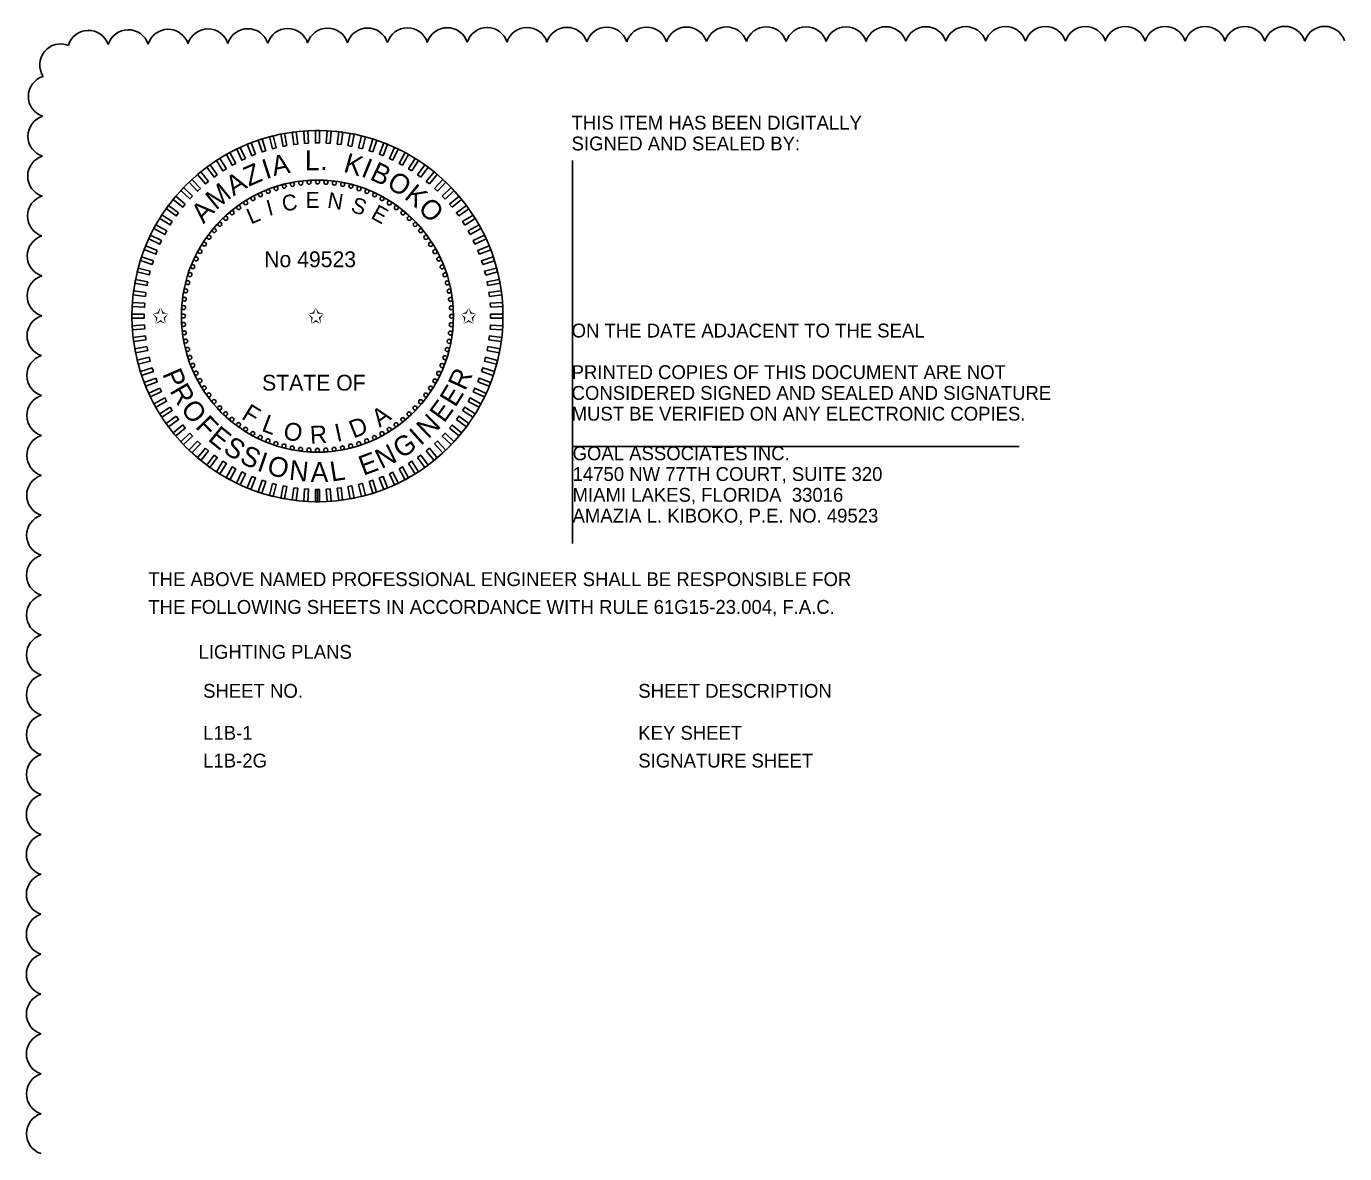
# Model space of a CAD drawing. Extents: x -811.2 to -755.6, y -2295.2 to -2235.1.
# Drawn here: x -783.68 to -777.02, y -2265.59 to -2259.9 of the extents above; entities that cross this region are included whole.
import ezdxf

# ---------------------------------------------------------------- set-up
doc = ezdxf.new("R2010")
doc.units = 0
for name, color, linetype in [('Cloud_dp', 7, 'Continuous'), ('Logo_dp', 7, 'Continuous'), ('NonPlottingEle_dp', 7, 'Continuous'), ('ScratchEle_dp', 7, 'Continuous'), ('TextMisc', 7, 'Continuous'), ('TextNotes', 7, 'Continuous')]:
    doc.layers.add(name, color=color, linetype=linetype)

msp = doc.modelspace()

# ---------------------------------------------------------------- linework, layer by layer
at = {"layer": 'Cloud_dp'}
for centre, start, end in [((-782.5594, -2260.0139), 17.87787, 162.87787), ((-782.3579, -2260.0127), 17.82689, 162.82689), ((-782.1564, -2260.0116), 17.78716, 162.78716), ((-781.9548, -2260.0107), 17.75505, 162.75505), ((-781.7533, -2260.0098), 17.72841, 162.72841), ((-781.5518, -2260.009), 17.70584, 162.70584), ((-781.3502, -2260.0084), 17.6864, 162.6864), ((-781.1487, -2260.0077), 17.66942, 162.66942), ((-780.9472, -2260.0072), 17.65443, 162.65443), ((-780.7456, -2260.0066), 17.64106, 162.64106), ((-780.5441, -2260.0062), 17.62905, 162.62905), ((-780.3425, -2260.0057), 17.61817, 162.61817), ((-780.141, -2260.0053), 17.60826, 162.60826), ((-779.9394, -2260.005), 17.59919, 162.59919), ((-779.7379, -2260.0046), 17.59084, 162.59084), ((-779.5364, -2260.0043), 17.58312, 162.58312), ((-779.3348, -2260.004), 17.57595, 162.57595), ((-779.1333, -2260.0038), 17.56928, 162.56928), ((-778.9317, -2260.0036), 17.56305, 162.56305), ((-778.7302, -2260.0033), 17.55721, 162.55721), ((-778.5286, -2260.0032), 17.55172, 162.55172), ((-778.3271, -2260.003), 17.54655, 162.54655), ((-778.1255, -2260.0028), 17.54167, 162.54167), ((-777.924, -2260.0027), 17.53705, 162.53705), ((-777.7224, -2260.0026), 17.53267, 162.53267), ((-777.5209, -2260.0025), 17.52851, 162.52851), ((-777.3194, -2260.0024), 17.52455, 162.52455), ((-777.1178, -2260.0023), 17.52079, 162.52079), ((-783.3652, -2260.0225), 18.59454, 163.59454), ((-783.1638, -2260.0193), 18.21421, 163.21421), ((-782.9624, -2260.0171), 18.04696, 163.04696), ((-782.7609, -2260.0154), 17.94666, 162.94666), ((-783.5053, -2260.0909), 68.43954, 213.43954), ((-783.563, -2260.2503), 106.80445, 251.80445), ((-783.565, -2260.4517), 107.04367, 252.04367), ((-783.5664, -2260.6532), 107.15618, 252.15618), ((-783.5675, -2260.8547), 107.22533, 252.22533), ((-783.5684, -2261.0562), 107.27338, 252.27338), ((-783.5691, -2261.2578), 107.30928, 252.30928), ((-783.5697, -2261.4593), 107.33743, 252.33743), ((-783.5703, -2261.6608), 107.36027, 252.36027), ((-783.5707, -2261.8624), 107.37928, 252.37928), ((-783.5711, -2262.0639), 107.39543, 252.39543), ((-783.5715, -2262.2655), 107.40937, 252.40937), ((-783.5717, -2262.467), 107.42156, 252.42156), ((-783.572, -2262.6685), 107.43234, 252.43234), ((-783.5722, -2262.8701), 107.44197, 252.44197), ((-783.5724, -2263.0716), 107.45063, 252.45063), ((-783.5726, -2263.2732), 107.45847, 252.45847), ((-783.5727, -2263.4747), 107.46563, 252.46563), ((-783.5728, -2263.6763), 107.47218, 252.47218), ((-783.5729, -2263.8778), 107.47822, 252.47822), ((-783.573, -2264.0794), 107.4838, 252.4838), ((-783.573, -2264.2809), 107.48899, 252.48899), ((-783.5731, -2264.4824), 107.49382, 252.49382), ((-783.5731, -2264.684), 107.49843, 252.49843), ((-783.573, -2264.8855), 107.51148, 252.51148), ((-783.573, -2265.0871), 107.53101, 252.53101), ((-783.5728, -2265.2886), 107.55191, 252.55191), ((-783.5726, -2265.4901), 107.57435, 252.57435)]:
    msp.add_arc(centre, 0.1057, start, end, dxfattribs=at)
at = {"layer": 'Logo_dp'}
for p, q in [((-782.2178, -2262.2978), (-782.218, -2262.2353)), ((-782.2078, -2262.2978), (-782.208, -2262.2353)), ((-782.1978, -2262.2978), (-782.198, -2262.2353))]:
    msp.add_line(p, q, dxfattribs=at)
for points in [[(-782.3618, -2260.4989), (-782.3816, -2260.5026), (-782.3933, -2260.4413), (-782.3735, -2260.4375)], [(-782.3074, -2260.4909), (-782.3274, -2260.4934), (-782.3352, -2260.4315), (-782.3152, -2260.4289)], [(-782.2526, -2260.4864), (-782.2727, -2260.4876), (-782.2767, -2260.4253), (-782.2565, -2260.424)], [(-782.1976, -2260.4853), (-782.2178, -2260.4853), (-782.2178, -2260.4228), (-782.1976, -2260.4228)], [(-782.1427, -2260.4876), (-782.1629, -2260.4864), (-782.1589, -2260.4241), (-782.1388, -2260.4253)], [(-782.088, -2260.4934), (-782.1081, -2260.4909), (-782.1002, -2260.429), (-782.0802, -2260.4315)], [(-782.0338, -2260.5027), (-782.0537, -2260.4989), (-782.042, -2260.4376), (-782.0221, -2260.4413)], [(-782.5712, -2260.5642), (-782.5894, -2260.5728), (-782.616, -2260.5163), (-782.5978, -2260.5077)], [(-782.5205, -2260.543), (-782.5392, -2260.5504), (-782.5622, -2260.4923), (-782.5434, -2260.4849)], [(-782.4685, -2260.525), (-782.4877, -2260.5312), (-782.507, -2260.4718), (-782.4878, -2260.4656)], [(-782.4156, -2260.5102), (-782.4351, -2260.5152), (-782.4506, -2260.4548), (-782.4311, -2260.4498)], [(-781.9803, -2260.5153), (-781.9999, -2260.5103), (-781.9844, -2260.4498), (-781.9648, -2260.4548)], [(-781.9277, -2260.5312), (-781.9469, -2260.525), (-781.9276, -2260.4656), (-781.9084, -2260.4719)], [(-781.8762, -2260.5505), (-781.895, -2260.543), (-781.872, -2260.485), (-781.8532, -2260.4924)], [(-781.826, -2260.5729), (-781.8443, -2260.5643), (-781.8177, -2260.5078), (-781.7994, -2260.5164)], [(-782.6681, -2260.616), (-782.6851, -2260.6268), (-782.7186, -2260.5741), (-782.7015, -2260.5633)], [(-782.6204, -2260.5886), (-782.6381, -2260.5983), (-782.6682, -2260.5436), (-782.6505, -2260.5339)], [(-781.7773, -2260.5984), (-781.795, -2260.5887), (-781.7649, -2260.534), (-781.7473, -2260.5437)], [(-781.7303, -2260.6269), (-781.7474, -2260.6161), (-781.7139, -2260.5634), (-781.6969, -2260.5742)], [(-782.7577, -2260.6796), (-782.7733, -2260.6925), (-782.8131, -2260.6443), (-782.7975, -2260.6315)], [(-782.7139, -2260.6464), (-782.7302, -2260.6583), (-782.7669, -2260.6078), (-782.7506, -2260.5959)], [(-781.6852, -2260.6584), (-781.7016, -2260.6465), (-781.6649, -2260.596), (-781.6485, -2260.6079)], [(-781.6422, -2260.6926), (-781.6578, -2260.6797), (-781.618, -2260.6316), (-781.6024, -2260.6445)], [(-782.7994, -2260.7155), (-782.8141, -2260.7293), (-782.8568, -2260.6838), (-782.8421, -2260.6699)], [(-781.6014, -2260.7294), (-781.6161, -2260.7156), (-781.5734, -2260.6701), (-781.5586, -2260.6839)], [(-782.8755, -2260.7947), (-782.8884, -2260.8102), (-782.9365, -2260.7704), (-782.9237, -2260.7549)], [(-782.8387, -2260.7539), (-782.8525, -2260.7686), (-782.898, -2260.7258), (-782.8842, -2260.7111)], [(-781.563, -2260.7687), (-781.5768, -2260.754), (-781.5313, -2260.7113), (-781.5175, -2260.726)], [(-781.5271, -2260.8104), (-781.54, -2260.7948), (-781.4919, -2260.755), (-781.479, -2260.7706)], [(-782.9097, -2260.8377), (-782.9216, -2260.8541), (-782.9721, -2260.8174), (-782.9603, -2260.801)], [(-781.4939, -2260.8542), (-781.5058, -2260.8379), (-781.4553, -2260.8012), (-781.4434, -2260.8175)], [(-782.9697, -2260.9298), (-782.9794, -2260.9475), (-783.0341, -2260.9174), (-783.0244, -2260.8997)], [(-782.9412, -2260.8828), (-782.952, -2260.8999), (-783.0047, -2260.8664), (-782.9939, -2260.8494)], [(-781.4635, -2260.9), (-781.4744, -2260.883), (-781.4216, -2260.8495), (-781.4108, -2260.8666)], [(-781.4361, -2260.9477), (-781.4458, -2260.93), (-781.3911, -2260.8999), (-781.3814, -2260.9176)], [(-782.9952, -2260.9785), (-783.0038, -2260.9968), (-783.0603, -2260.9702), (-783.0517, -2260.9519)], [(-781.4117, -2260.9969), (-781.4203, -2260.9787), (-781.3638, -2260.9521), (-781.3552, -2260.9704)], [(-783.0176, -2261.0287), (-783.0251, -2261.0475), (-783.0831, -2261.0245), (-783.0757, -2261.0057)], [(-781.3905, -2261.0477), (-781.3979, -2261.0289), (-781.3399, -2261.0059), (-781.3324, -2261.0247)], [(-783.0369, -2261.0802), (-783.0431, -2261.0994), (-783.1025, -2261.0801), (-783.0963, -2261.0609)], [(-781.3725, -2261.0996), (-781.3787, -2261.0804), (-781.3193, -2261.0611), (-781.3131, -2261.0803)], [(-783.0654, -2261.1863), (-783.0692, -2261.2062), (-783.1306, -2261.1945), (-783.1268, -2261.1746)], [(-783.0528, -2261.1328), (-783.0578, -2261.1524), (-783.1183, -2261.1368), (-783.1133, -2261.1173)], [(-781.3577, -2261.1526), (-781.3628, -2261.133), (-781.3023, -2261.1175), (-781.2973, -2261.137)], [(-781.3464, -2261.2063), (-781.3502, -2261.1865), (-781.2888, -2261.1748), (-781.285, -2261.1946)], [(-783.0747, -2261.2405), (-783.0772, -2261.2606), (-783.1391, -2261.2527), (-783.1366, -2261.2327)], [(-781.3384, -2261.2607), (-781.3409, -2261.2407), (-781.279, -2261.2329), (-781.2765, -2261.2529)], [(-783.0805, -2261.2952), (-783.0817, -2261.3153), (-783.1441, -2261.3114), (-783.1428, -2261.2913)], [(-781.3339, -2261.3155), (-781.3351, -2261.2954), (-781.2728, -2261.2915), (-781.2716, -2261.3116)], [(-783.0828, -2261.3501), (-783.0828, -2261.3703), (-783.1453, -2261.3703), (-783.1453, -2261.3501)], [(-781.3328, -2261.3705), (-781.3328, -2261.3503), (-781.2703, -2261.3503), (-781.2703, -2261.3705)], [(-783.0818, -2261.4051), (-783.0805, -2261.4252), (-783.1428, -2261.4291), (-783.1441, -2261.409)], [(-781.3351, -2261.4254), (-781.3339, -2261.4053), (-781.2716, -2261.4092), (-781.2728, -2261.4293)], [(-783.0772, -2261.4599), (-783.0747, -2261.4799), (-783.1366, -2261.4877), (-783.1392, -2261.4677)], [(-781.341, -2261.4801), (-781.3384, -2261.4601), (-781.2765, -2261.4679), (-781.279, -2261.4879)], [(-783.0693, -2261.5143), (-783.0655, -2261.5341), (-783.1268, -2261.5458), (-783.1306, -2261.526)], [(-783.0579, -2261.568), (-783.0529, -2261.5876), (-783.1133, -2261.6031), (-783.1184, -2261.5836)], [(-781.3628, -2261.5878), (-781.3578, -2261.5682), (-781.2973, -2261.5838), (-781.3023, -2261.6033)], [(-781.3502, -2261.5343), (-781.3464, -2261.5144), (-781.2851, -2261.5261), (-781.2889, -2261.546)], [(-783.0432, -2261.621), (-783.0369, -2261.6402), (-783.0963, -2261.6595), (-783.1025, -2261.6403)], [(-781.3788, -2261.6404), (-781.3725, -2261.6212), (-781.3131, -2261.6405), (-781.3194, -2261.6597)], [(-783.0251, -2261.673), (-783.0177, -2261.6917), (-783.0758, -2261.7147), (-783.0832, -2261.6959)], [(-781.398, -2261.6919), (-781.3906, -2261.6731), (-781.3325, -2261.6961), (-781.3399, -2261.7149)], [(-783.0039, -2261.7237), (-782.9953, -2261.7419), (-783.0518, -2261.7685), (-783.0604, -2261.7502)], [(-782.9795, -2261.7729), (-782.9698, -2261.7906), (-783.0245, -2261.8207), (-783.0342, -2261.803)], [(-781.4459, -2261.7908), (-781.4362, -2261.7731), (-781.3815, -2261.8032), (-781.3912, -2261.8209)], [(-781.4204, -2261.7421), (-781.4118, -2261.7238), (-781.3553, -2261.7504), (-781.3639, -2261.7687)], [(-782.9521, -2261.8206), (-782.9413, -2261.8376), (-782.994, -2261.8711), (-783.0048, -2261.854)], [(-781.4745, -2261.8378), (-781.4636, -2261.8207), (-781.4109, -2261.8542), (-781.4217, -2261.8712)], [(-782.9217, -2261.8664), (-782.9099, -2261.8827), (-782.9604, -2261.9194), (-782.9722, -2261.9031)], [(-781.5059, -2261.8829), (-781.494, -2261.8665), (-781.4435, -2261.9032), (-781.4554, -2261.9196)], [(-782.8885, -2261.9102), (-782.8757, -2261.9258), (-782.9238, -2261.9656), (-782.9366, -2261.95)], [(-782.8527, -2261.9519), (-782.8388, -2261.9666), (-782.8844, -2262.0093), (-782.8982, -2261.9946)], [(-781.5769, -2261.9667), (-781.5631, -2261.952), (-781.5176, -2261.9948), (-781.5314, -2262.0095)], [(-781.5401, -2261.9259), (-781.5272, -2261.9104), (-781.4791, -2261.9502), (-781.492, -2261.9657)], [(-782.8142, -2261.9912), (-782.7995, -2262.005), (-782.8423, -2262.0505), (-782.857, -2262.0367)], [(-782.7734, -2262.028), (-782.7579, -2262.0409), (-782.7977, -2262.089), (-782.8132, -2262.0761)], [(-781.6579, -2262.041), (-781.6423, -2262.0281), (-781.6025, -2262.0763), (-781.6181, -2262.0891)], [(-781.6162, -2262.0051), (-781.6015, -2261.9913), (-781.5588, -2262.0368), (-781.5735, -2262.0507)], [(-782.7304, -2262.0622), (-782.7141, -2262.0741), (-782.7508, -2262.1246), (-782.7671, -2262.1127)], [(-782.6853, -2262.0937), (-782.6682, -2262.1045), (-782.7017, -2262.1572), (-782.7187, -2262.1464)], [(-781.7475, -2262.1046), (-781.7305, -2262.0938), (-781.697, -2262.1465), (-781.7141, -2262.1573)], [(-781.7017, -2262.0742), (-781.6854, -2262.0623), (-781.6487, -2262.1129), (-781.665, -2262.1247)], [(-782.6383, -2262.1222), (-782.6206, -2262.1319), (-782.6507, -2262.1866), (-782.6684, -2262.1769)], [(-782.5896, -2262.1477), (-782.5713, -2262.1563), (-782.5979, -2262.2128), (-782.6162, -2262.2042)], [(-782.5394, -2262.1701), (-782.5206, -2262.1776), (-782.5436, -2262.2356), (-782.5624, -2262.2282)], [(-781.8952, -2262.1776), (-781.8764, -2262.1702), (-781.8534, -2262.2283), (-781.8722, -2262.2357)], [(-781.8445, -2262.1564), (-781.8262, -2262.1478), (-781.7996, -2262.2043), (-781.8179, -2262.2129)], [(-781.7952, -2262.132), (-781.7775, -2262.1223), (-781.7474, -2262.177), (-781.7651, -2262.1867)], [(-782.4879, -2262.1894), (-782.4687, -2262.1956), (-782.488, -2262.255), (-782.5072, -2262.2487)], [(-782.4353, -2262.2053), (-782.4157, -2262.2103), (-782.4313, -2262.2708), (-782.4508, -2262.2658)], [(-782.3818, -2262.2179), (-782.362, -2262.2217), (-782.3737, -2262.283), (-782.3935, -2262.2793)], [(-782.3276, -2262.2272), (-782.3076, -2262.2297), (-782.3154, -2262.2916), (-782.3354, -2262.2891)], [(-782.2729, -2262.233), (-782.2528, -2262.2342), (-782.2567, -2262.2966), (-782.2768, -2262.2953)], [(-782.218, -2262.2353), (-782.1978, -2262.2353), (-782.1978, -2262.2978), (-782.218, -2262.2978)], [(-782.163, -2262.2342), (-782.1429, -2262.233), (-782.139, -2262.2953), (-782.1591, -2262.2966)], [(-782.1082, -2262.2297), (-782.0882, -2262.2272), (-782.0804, -2262.2891), (-782.1004, -2262.2917)], [(-782.0539, -2262.2217), (-782.034, -2262.218), (-782.0223, -2262.2793), (-782.0422, -2262.2831)], [(-782.0001, -2262.2104), (-781.9805, -2262.2054), (-781.965, -2262.2658), (-781.9845, -2262.2709)], [(-781.9471, -2262.1957), (-781.9279, -2262.1894), (-781.9086, -2262.2488), (-781.9278, -2262.255)]]:
    msp.add_lwpolyline(points, close=True, dxfattribs=at)
for centre in [(-782.4166, -2260.7158), (-782.3757, -2260.704), (-782.3342, -2260.6947), (-782.2922, -2260.6881), (-782.2498, -2260.6841), (-782.2072, -2260.6828), (-782.1647, -2260.6842), (-782.1223, -2260.6882), (-782.0803, -2260.6949), (-782.0388, -2260.7043), (-781.9979, -2260.7162), (-782.5337, -2260.7664), (-782.4958, -2260.7471), (-782.4567, -2260.7302), (-781.9579, -2260.7306), (-781.9189, -2260.7476), (-781.8809, -2260.7669), (-782.6392, -2260.8379), (-782.6056, -2260.8119), (-782.5703, -2260.788), (-781.8443, -2260.7886), (-781.8092, -2260.8125), (-781.7755, -2260.8387), (-782.7013, -2260.8961), (-782.6712, -2260.8661), (-781.7436, -2260.8668), (-781.7136, -2260.897), (-782.7556, -2260.9616), (-782.7295, -2260.928), (-781.6855, -2260.9289), (-781.6594, -2260.9626), (-782.8012, -2261.0334), (-782.7795, -2260.9968), (-781.6355, -2260.9978), (-781.6139, -2261.0344), (-782.8375, -2261.1104), (-782.8206, -2261.0713), (-781.5946, -2261.0724), (-781.5777, -2261.1114), (-782.852, -2261.1504), (-781.5633, -2261.1515), (-782.8732, -2261.2328), (-782.8639, -2261.1913), (-781.5515, -2261.1924), (-781.5422, -2261.2339), (-782.8839, -2261.3172), (-782.8799, -2261.2748), (-781.5356, -2261.276), (-782.8853, -2261.3597), (-781.5316, -2261.3183), (-781.5303, -2261.3609), (-782.884, -2261.4023), (-782.88, -2261.4447), (-781.5358, -2261.4458), (-781.5317, -2261.4034), (-782.8734, -2261.4867), (-781.5425, -2261.4878), (-782.8641, -2261.5282), (-782.8523, -2261.5691), (-781.5637, -2261.5702), (-781.5518, -2261.5293), (-782.8379, -2261.6092), (-782.821, -2261.6482), (-781.5951, -2261.6493), (-781.5781, -2261.6102), (-782.8018, -2261.6862), (-781.6144, -2261.6872), (-782.7801, -2261.7228), (-782.7562, -2261.7581), (-781.6601, -2261.759), (-781.6361, -2261.7238), (-782.7302, -2261.7917), (-782.7021, -2261.8236), (-781.7143, -2261.8245), (-781.6862, -2261.7926), (-782.672, -2261.8538), (-782.6401, -2261.8819), (-782.6065, -2261.9081), (-781.8101, -2261.9087), (-781.7764, -2261.8827), (-781.7445, -2261.8545), (-782.5713, -2261.932), (-782.5347, -2261.9537), (-782.4968, -2261.9731), (-781.9199, -2261.9735), (-781.8819, -2261.9542), (-781.8453, -2261.9326), (-782.4577, -2261.99), (-782.4177, -2262.0044), (-782.3768, -2262.0163), (-782.3353, -2262.0257), (-782.2933, -2262.0324), (-782.2509, -2262.0364), (-782.2078, -2262.0378), (-782.1658, -2262.0365), (-782.1235, -2262.0325), (-782.0814, -2262.0259), (-782.0399, -2262.0166), (-781.999, -2262.0048), (-781.9589, -2261.9904)]:
    msp.add_circle(centre, 0.01, dxfattribs=at)
at = {"layer": 'NonPlottingEle_dp'}
for radius in [0.9375, 0.6875]:
    msp.add_circle((-782.2078, -2261.3603), radius, dxfattribs=at)
at = {"layer": 'ScratchEle_dp'}
for p, q in [((-780.9186, -2260.5734), (-780.9186, -2262.5081)), ((-780.9186, -2262.0181), (-778.6618, -2262.0181))]:
    msp.add_line(p, q, dxfattribs=at)

# ---------------------------------------------------------------- texts
at = {"layer": 'Logo_dp'}
for s, rotation, p in [('I', 14.81888, (-782.4534, -2260.8551)), ('C', 8.98261, (-782.3808, -2260.8324)), ('E', 359.96623, (-782.2681, -2260.8135)), ('N', 350.64643, (-782.1612, -2260.8121)), ('S', 341.03996, (-782.0441, -2260.8309)), ('L', 23.30524, (-782.544, -2260.898)), ('E', 331.16864, (-781.9426, -2260.8635))]:
    msp.add_text(s, height=0.08, rotation=rotation, dxfattribs=at).set_placement(p)
for p in [(-783.0428, -2261.3983), (-782.2581, -2261.3983), (-781.4862, -2261.3983)]:
    msp.add_text('✩', height=0.08, dxfattribs=at).set_placement(p)
at = {"layer": 'TextMisc'}
for s, height, p in [('THIS ITEM HAS BEEN DIGITALLY', 0.07, (-780.9235, -2260.4183)), ('SIGNED AND SEALED BY:', 0.07, (-780.9235, -2260.5233)), ('No 49523', 0.08, (-782.4768, -2261.1131)), ('ON THE DATE ADJACENT TO THE SEAL', 0.07, (-780.9235, -2261.4683)), ('PRINTED COPIES OF THIS DOCUMENT ARE NOT ', 0.07, (-780.9235, -2261.6783)), ('STATE OF', 0.08, (-782.4875, -2261.7365)), ('CONSIDERED SIGNED AND SEALED AND SIGNATURE ', 0.07, (-780.9235, -2261.7833)), ('MUST BE VERIFIED ON ANY ELECTRONIC COPIES.', 0.07, (-780.9235, -2261.8883)), ('GOAL ASSOCIATES INC.', 0.07, (-780.9186, -2262.0881)), ('14750 NW 77TH COURT, SUITE 320', 0.07, (-780.9186, -2262.1931)), ('MIAMI LAKES, FLORIDA  33016', 0.07, (-780.9186, -2262.2981)), ('AMAZIA L. KIBOKO, P.E. NO. 49523', 0.07, (-780.9186, -2262.4031)), ('THE ABOVE NAMED PROFESSIONAL ENGINEER SHALL BE RESPONSIBLE FOR ', 0.07, (-783.0626, -2262.7243)), ('THE FOLLOWING SHEETS IN ACCORDANCE WITH RULE 61G15-23.004, F.A.C.', 0.07, (-783.0626, -2262.8643)), ('LIGHTING PLANS', 0.07, (-782.8089, -2263.0913))]:
    msp.add_text(s, height=height, dxfattribs=at).set_placement(p)
for s, height, rotation, p in [('I', 0.1, 17.68363, (-782.4679, -2260.6694)), ('A', 0.1, 11.91844, (-782.4286, -2260.6534)), ('L', 0.1, 359.96623, (-782.2714, -2260.623)), ('K', 0.1, 344.27273, (-782.0807, -2260.6302)), ('I', 0.1, 337.77772, (-781.9921, -2260.652)), ('Z', 0.1, 23.30524, (-782.5548, -2260.707)), ('.', 0.1, 353.78581, (-782.1947, -2260.6201)), ('B', 0.1, 334.48695, (-781.9482, -2260.6673)), ('O', 0.1, 327.82385, (-781.8635, -2260.7059)), ('M', 0.1, 39.30005, (-782.7212, -2260.8277)), ('A', 0.1, 31.46601, (-782.6322, -2260.7556)), ('K', 0.1, 321.0594, (-781.7739, -2260.7631)), ('O', 0.1, 314.20329, (-781.7043, -2260.8207)), ('A', 0.1, 46.80938, (-782.7835, -2260.8962)), ('P', 0.1, 293.19548, (-782.9935, -2261.6519)), ('R', 0.1, 65.28865, (-781.4614, -2261.7412)), ('R', 0.1, 300.25949, (-782.9566, -2261.7378)), ('E', 0.1, 58.61694, (-781.5106, -2261.8252)), ('O', 0.1, 307.26617, (-782.9025, -2261.8296)), ('F', 0.09, 328.53399, (-782.5962, -2261.8756)), ('A', 0.09, 35.54629, (-781.8934, -2261.9249)), ('E', 0.1, 53.99864, (-781.5679, -2261.9039)), ('F', 0.1, 314.20329, (-782.8291, -2261.9221)), ('L', 0.09, 339.48752, (-782.495, -2261.9386)), ('O', 0.09, 348.08156, (-782.3856, -2261.9792)), ('I', 0.09, 12.52485, (-782.1092, -2261.9963)), ('D', 0.09, 22.22228, (-782.0251, -2261.9794)), ('N', 0.1, 44.34211, (-781.6479, -2261.9838)), ('E', 0.1, 321.0594, (-782.7657, -2261.9857)), ('R', 0.09, 3.10738, (-782.2434, -2262.0054)), ('G', 0.1, 34.11362, (-781.7834, -2262.084)), ('I', 0.1, 41.83906, (-781.6873, -2262.018)), ('S', 0.1, 327.82385, (-782.6895, -2262.0462)), ('S', 0.1, 334.48695, (-782.6064, -2262.0976)), ('N', 0.1, 26.0618, (-781.8846, -2262.1342)), ('I', 0.1, 341.03996, (-782.5178, -2262.1389)), ('O', 0.1, 344.27273, (-782.4687, -2262.1565)), ('N', 0.1, 353.78581, (-782.3543, -2262.1864)), ('A', 0.1, 359.96623, (-782.242, -2262.1974)), ('L', 0.1, 8.98261, (-782.1363, -2262.1966)), ('E', 0.1, 20.51248, (-781.9761, -2262.1675))]:
    msp.add_text(s, height=height, rotation=rotation, dxfattribs=at).set_placement(p)
at = {"layer": 'TextNotes'}
for s, p in [('SHEET NO.', (-782.7855, -2263.2883)), ('SHEET DESCRIPTION', (-780.5865, -2263.2883)), ('L1B-1', (-782.7855, -2263.5005)), ('KEY SHEET', (-780.5865, -2263.5005)), ('L1B-2G', (-782.7855, -2263.6405)), ('SIGNATURE SHEET', (-780.5865, -2263.6405))]:
    msp.add_text(s, height=0.07, dxfattribs=at).set_placement(p)

doc.saveas('drawing.dxf')
